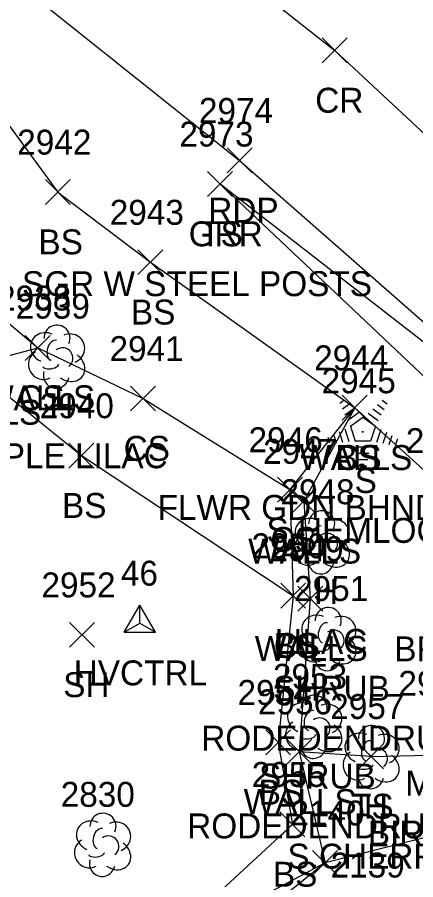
# Model space of a CAD drawing. Extents: x 1499292 to 1501024, y 534584 to 538043.
# Drawn here: x 1499749.5 to 1499781.4, y 537664.7 to 537733.8 of the extents above; entities that cross this region are included whole.
import ezdxf

# ---------------------------------------------------------------- set-up
doc = ezdxf.new("R2010")
doc.units = 0
for name, color, linetype in [('C_A', 7, 'Continuous'), ('C_I', 7, 'Continuous'), ('CPSM', 7, 'Continuous'), ('L_A', 7, 'Continuous'), ('L_C', 7, 'Continuous'), ('L_I', 7, 'Continuous'), ('L_TIC', 7, 'Continuous'), ('LAWA', 7, 'Continuous'), ('LELB', 7, 'Continuous'), ('LSH', 7, 'Continuous'), ('LTC', 7, 'Continuous'), ('LTD', 7, 'Continuous'), ('LWS', 7, 'Continuous'), ('P_A', 7, 'Continuous'), ('P_I', 7, 'Continuous'), ('P_TIC', 7, 'Continuous'), ('PET', 7, 'Continuous'), ('PRC', 7, 'Continuous'), ('R_A', 7, 'Continuous'), ('R_C', 7, 'Continuous'), ('R_I', 7, 'Continuous'), ('R_TIC', 7, 'Continuous'), ('RGR', 7, 'Continuous'), ('S_C', 7, 'Continuous')]:
    doc.layers.add(name, color=color, linetype=linetype)

msp = doc.modelspace()

# ---------------------------------------------------------------- linework, layer by layer
at = {"layer": 'CPSM'}
for p, q in [((1499758.044, 537684.529), (1499759.294, 537686.694)), ((1499760.544, 537684.529), (1499759.294, 537686.694)), ((1499759.294, 537685.25), (1499759.294, 537686.694)), ((1499758.044, 537684.529), (1499759.294, 537685.25)), ((1499759.294, 537685.25), (1499759.294, 537685.25)), ((1499759.294, 537685.25), (1499760.544, 537684.529)), ((1499758.044, 537684.529), (1499760.544, 537684.529))]:
    msp.add_line(p, q, dxfattribs=at)
at = {"layer": 'L_TIC'}
for points in [[(1499751.712, 537718.821), (1499753.712, 537720.821)], [(1499753.712, 537718.821), (1499751.712, 537720.821)], [(1499764.726, 537719.467), (1499766.726, 537721.467)], [(1499766.726, 537719.467), (1499764.726, 537721.467)], [(1499759.138, 537713.193), (1499761.138, 537715.193)], [(1499761.138, 537713.193), (1499759.138, 537715.193)], [(1499750.097, 537706.315), (1499752.097, 537708.315)], [(1499752.097, 537706.315), (1499750.097, 537708.315)], [(1499750.097, 537706.315), (1499752.097, 537708.315)], [(1499752.097, 537706.315), (1499750.097, 537708.315)], [(1499758.552, 537702.258), (1499760.552, 537704.258)], [(1499760.552, 537702.258), (1499758.552, 537704.258)], [(1499775.543, 537701.52), (1499777.543, 537703.52)], [(1499777.543, 537701.52), (1499775.543, 537703.52)], [(1499775.543, 537701.52), (1499777.543, 537703.52)], [(1499777.543, 537701.52), (1499775.543, 537703.52)], [(1499775.543, 537701.52), (1499777.543, 537703.52)], [(1499777.543, 537701.52), (1499775.543, 537703.52)], [(1499753.605, 537697.679), (1499755.605, 537699.679)], [(1499755.605, 537697.679), (1499753.605, 537699.679)], [(1499770.334, 537694.953), (1499772.334, 537696.953)], [(1499772.334, 537694.953), (1499770.334, 537696.953)], [(1499770.334, 537694.953), (1499772.334, 537696.953)], [(1499772.334, 537694.953), (1499770.334, 537696.953)], [(1499771.443, 537694.018), (1499773.443, 537696.018)], [(1499773.443, 537694.018), (1499771.443, 537696.018)], [(1499770.599, 537686.444), (1499772.599, 537688.444)], [(1499772.599, 537686.444), (1499770.599, 537688.444)], [(1499770.599, 537686.444), (1499772.599, 537688.444)], [(1499772.599, 537686.444), (1499770.599, 537688.444)], [(1499771.971, 537686.21), (1499773.971, 537688.21)], [(1499773.971, 537686.21), (1499771.971, 537688.21)], [(1499753.656, 537683.305), (1499755.656, 537685.305)], [(1499755.656, 537683.305), (1499753.656, 537685.305)], [(1499769.394, 537674.679), (1499771.394, 537676.679)], [(1499771.394, 537674.679), (1499769.394, 537676.679)], [(1499771.085, 537673.925), (1499773.085, 537675.925)], [(1499773.085, 537673.925), (1499771.085, 537675.925)], [(1499776.835, 537673.552), (1499778.835, 537675.552)], [(1499778.835, 537673.552), (1499776.835, 537675.552)], [(1499770.532, 537668.102), (1499772.532, 537670.102)], [(1499772.532, 537668.102), (1499770.532, 537670.102)], [(1499773.16, 537665.013), (1499775.16, 537667.013)], [(1499775.16, 537665.013), (1499773.16, 537667.013)], [(1499773.16, 537665.013), (1499775.16, 537667.013)], [(1499775.16, 537665.013), (1499773.16, 537667.013)]]:
    msp.add_lwpolyline(points, dxfattribs=at)
at = {"layer": 'LAWA'}
msp.add_lwpolyline([(1499794.252, 537673.216), (1499784.112, 537668.524), (1499774.16, 537666.013), (1499760.161, 537658.549), (1499756.138, 537654.928), (1499740.504, 537649.758), (1499726.858, 537641.254), (1499716.884, 537640.029), (1499711.646, 537641.29), (1499703.308, 537651.197), (1499688.979, 537659.909), (1499670.84, 537674.411)], dxfattribs=at)
at = {"layer": 'LELB'}
for points in [[(1499673.505, 537786.342), (1499677.07, 537783.592), (1499700.821, 537763.481), (1499719.743, 537752.304), (1499723.657, 537747.33), (1499740.89, 537735.965), (1499752.712, 537719.821), (1499760.138, 537714.193), (1499776.543, 537702.52), (1499783.898, 537695.878)], [(1499765.726, 537720.467), (1499786.683, 537700.702), (1499803.043, 537683.466)], [(1499737.647, 537718.705), (1499751.097, 537707.315), (1499759.552, 537703.258), (1499771.334, 537695.953)], [(1499731.101, 537702.105), (1499743.79, 537705.244), (1499746.925, 537704.877), (1499754.605, 537698.679), (1499771.599, 537687.444), (1499770.394, 537675.679), (1499771.532, 537669.102)], [(1499776.543, 537702.52), (1499771.334, 537695.953), (1499771.599, 537687.444)], [(1499777.835, 537674.552), (1499772.085, 537674.925)], [(1499777.835, 537674.552), (1499786.002, 537674.728)], [(1499771.532, 537669.102), (1499760.161, 537658.549)]]:
    msp.add_lwpolyline(points, dxfattribs=at)
at = {"layer": 'LSH'}
for p, q in [((1499774.365, 537684.016), (1499774.365, 537684.016)), ((1499774.365, 537684.016), (1499774.365, 537684.016)), ((1499773.233, 537676.975), (1499773.233, 537676.975)), ((1499773.233, 537676.975), (1499773.233, 537676.975))]:
    msp.add_line(p, q, dxfattribs=at)
for centre in [(1499774.412, 537685.45), (1499773.28, 537678.409)]:
    msp.add_arc(centre, 1.047, 335.52715, 180.95627, dxfattribs=at)
for centre, major_axis, ratio, start_param, end_param in [((1499773.573, 537684.683), (1.21, -0.512), 0.895232, 1.570796, 4.712389), ((1499775.407, 537684.6), (-1.141, -0.483), 0.949671, 1.570796, 4.712389), ((1499774.157, 537684.474), (-0.208, -0.792), 0.645439, 3.141593, 6.283185), ((1499773.282, 537683.308), (0.584, -1.042), 0.959034, 3.141593, 6.283185), ((1499774.865, 537683.85), (-0.5, 0.667), 0.989748, 3.141593, 6.283185), ((1499775.365, 537683.183), (-1.09, 0.792), 0.841452, 1.570796, 4.712389), ((1499774.365, 537682.516), (0.265, 1.061), 0.942809, 1.570796, 4.712389), ((1499773.907, 537683.266), (-0.625, -0.083), 0.423636, 0, 3.141593), ((1499772.442, 537677.642), (1.21, -0.512), 0.895232, 1.570796, 4.712389), ((1499774.275, 537677.559), (-1.141, -0.483), 0.949671, 1.570796, 4.712389), ((1499773.025, 537677.433), (-0.208, -0.792), 0.645439, 3.141593, 6.283185), ((1499772.15, 537676.267), (0.584, -1.042), 0.959034, 3.141593, 6.283185), ((1499773.733, 537676.808), (-0.5, 0.667), 0.989748, 3.141593, 6.283185), ((1499774.234, 537676.142), (-1.09, 0.792), 0.841452, 1.570796, 4.712389), ((1499772.775, 537676.225), (-0.625, -0.083), 0.423636, 0, 3.141593), ((1499773.234, 537675.475), (0.265, 1.061), 0.942809, 1.570796, 4.712389)]:
    msp.add_ellipse(centre, major_axis=major_axis, ratio=ratio, start_param=start_param, end_param=end_param, dxfattribs=at)
at = {"layer": 'LTC'}
for p, q in [((1499775.336, 537702.888), (1499775.69, 537703.146)), ((1499778.734, 537703.129), (1499779.153, 537702.824)), ((1499775.545, 537702.423), (1499776.074, 537702.807)), ((1499775.755, 537701.957), (1499776.458, 537702.468)), ((1499775.964, 537701.491), (1499776.843, 537702.129)), ((1499777.992, 537702.432), (1499778.671, 537701.938)), ((1499778.363, 537702.78), (1499778.912, 537702.381)), ((1499776.189, 537701.036), (1499777.201, 537701.771)), ((1499777.201, 537701.771), (1499778.198, 537701.046)), ((1499777.621, 537702.084), (1499778.43, 537701.495)), ((1499775.734, 537700.817), (1499776.065, 537699.798)), ((1499776.189, 537701.036), (1499776.576, 537699.843)), ((1499778.198, 537701.046), (1499777.806, 537699.843)), ((1499778.635, 537700.775), (1499778.297, 537699.735)), ((1499774.368, 537700.167), (1499774.52, 537699.699)), ((1499774.824, 537700.384), (1499775.035, 537699.732)), ((1499775.279, 537700.601), (1499775.55, 537699.765)), ((1499779.08, 537700.524), (1499778.792, 537699.64)), ((1499779.524, 537700.274), (1499779.287, 537699.545)), ((1499777.806, 537699.843), (1499776.576, 537699.843)), ((1499779.968, 537700.024), (1499779.782, 537699.45)), ((1499777.768, 537699.343), (1499776.623, 537699.343)), ((1499777.684, 537698.843), (1499776.696, 537698.843)), ((1499777.601, 537698.343), (1499776.769, 537698.343)), ((1499777.517, 537697.843), (1499776.842, 537697.843))]:
    msp.add_line(p, q, dxfattribs=at)
at = {"layer": 'LTD'}
for p, q in [((1499752.598, 537706.666), (1499752.598, 537706.666)), ((1499752.598, 537706.666), (1499752.598, 537706.666)), ((1499773.838, 537691.777), (1499773.838, 537691.777)), ((1499773.838, 537691.777), (1499773.838, 537691.777)), ((1499777.835, 537674.552), (1499777.835, 537674.552)), ((1499777.835, 537674.552), (1499777.835, 537674.552)), ((1499756.287, 537667.508), (1499756.287, 537667.508)), ((1499756.287, 537667.508), (1499756.287, 537667.508))]:
    msp.add_line(p, q, dxfattribs=at)
for centre in [(1499752.644, 537708.1), (1499773.884, 537693.211), (1499777.882, 537675.986), (1499756.334, 537668.942)]:
    msp.add_arc(centre, 1.047, 335.52715, 180.95627, dxfattribs=at)
for centre, major_axis, ratio, start_param, end_param in [((1499751.806, 537707.333), (1.21, -0.512), 0.895232, 1.570796, 4.712389), ((1499753.639, 537707.25), (-1.141, -0.483), 0.949671, 1.570796, 4.712389), ((1499752.389, 537707.125), (-0.208, -0.792), 0.645439, 3.141593, 6.283185), ((1499751.515, 537705.958), (0.584, -1.042), 0.959034, 3.141593, 6.283185), ((1499753.098, 537706.5), (-0.5, 0.667), 0.989748, 3.141593, 6.283185), ((1499753.598, 537705.833), (-1.09, 0.792), 0.841452, 1.570796, 4.712389), ((1499752.14, 537705.916), (-0.625, -0.083), 0.423636, 0, 3.141593), ((1499752.598, 537705.166), (0.265, 1.061), 0.942809, 1.570796, 4.712389), ((1499773.046, 537692.444), (1.21, -0.512), 0.895232, 1.570796, 4.712389), ((1499774.879, 537692.361), (-1.141, -0.483), 0.949671, 1.570796, 4.712389), ((1499773.629, 537692.235), (-0.208, -0.792), 0.645439, 3.141593, 6.283185), ((1499774.338, 537691.611), (-0.5, 0.667), 0.989748, 3.141593, 6.283185), ((1499772.754, 537691.069), (0.584, -1.042), 0.959034, 3.141593, 6.283185), ((1499774.838, 537690.944), (-1.09, 0.792), 0.841452, 1.570796, 4.712389), ((1499773.379, 537691.027), (-0.625, -0.083), 0.423636, 0, 3.141593), ((1499773.838, 537690.277), (0.265, 1.061), 0.942809, 1.570796, 4.712389), ((1499777.044, 537675.218), (1.21, -0.512), 0.895232, 1.570796, 4.712389), ((1499777.627, 537675.01), (-0.208, -0.792), 0.645439, 3.141593, 6.283185), ((1499778.877, 537675.135), (-1.141, -0.483), 0.949671, 1.570796, 4.712389), ((1499778.335, 537674.385), (-0.5, 0.667), 0.989748, 3.141593, 6.283185), ((1499776.752, 537673.843), (0.584, -1.042), 0.959034, 3.141593, 6.283185), ((1499778.835, 537673.719), (-1.09, 0.792), 0.841452, 1.570796, 4.712389), ((1499777.377, 537673.802), (-0.625, -0.083), 0.423636, 0, 3.141593), ((1499777.836, 537673.052), (0.265, 1.061), 0.942809, 1.570796, 4.712389), ((1499755.495, 537668.175), (1.21, -0.512), 0.895232, 1.570796, 4.712389), ((1499757.329, 537668.092), (-1.141, -0.483), 0.949671, 1.570796, 4.712389), ((1499756.079, 537667.967), (-0.208, -0.792), 0.645439, 3.141593, 6.283185), ((1499756.787, 537667.342), (-0.5, 0.667), 0.989748, 3.141593, 6.283185), ((1499755.204, 537666.8), (0.584, -1.042), 0.959034, 3.141593, 6.283185), ((1499757.287, 537666.675), (-1.09, 0.792), 0.841452, 1.570796, 4.712389), ((1499755.829, 537666.758), (-0.625, -0.083), 0.423636, 0, 3.141593), ((1499756.288, 537666.008), (0.265, 1.061), 0.942809, 1.570796, 4.712389)]:
    msp.add_ellipse(centre, major_axis=major_axis, ratio=ratio, start_param=start_param, end_param=end_param, dxfattribs=at)
at = {"layer": 'LWS'}
for points in [[(1499743.79, 537705.244), (1499746.766, 537706.161), (1499751.097, 537707.315)], [(1499776.543, 537702.52), (1499772.443, 537695.018), (1499772.971, 537687.21), (1499772.085, 537674.925)], [(1499772.085, 537674.925), (1499774.16, 537666.013)], [(1499774.16, 537666.013), (1499761.796, 537656.084), (1499756.809, 537653.017), (1499742.21, 537646.621), (1499726.858, 537641.254)]]:
    msp.add_lwpolyline(points, dxfattribs=at)
at = {"layer": 'P_TIC'}
for points in [[(1499773.937, 537730.181), (1499775.937, 537732.181)], [(1499775.937, 537730.181), (1499773.937, 537732.181)], [(1499766.298, 537721.36), (1499768.298, 537723.36)], [(1499768.298, 537721.36), (1499766.298, 537723.36)]]:
    msp.add_lwpolyline(points, dxfattribs=at)
at = {"layer": 'PET'}
msp.add_lwpolyline([(1499310.023, 537983.746), (1499343.075, 537969.541), (1499383.731, 537949.439), (1499427.71, 537927.425), (1499464.171, 537907.983), (1499500.199, 537887.497), (1499544.495, 537863.142), (1499587.74, 537838.677), (1499616.247, 537822.183), (1499651.021, 537801.554), (1499676.536, 537785.628), (1499704.158, 537768.574), (1499722.55, 537756.398), (1499745.414, 537739.8), (1499767.298, 537722.36), (1499790.892, 537701.646), (1499806.057, 537686.036), (1499813.912, 537693.068), (1499820.533, 537699.08)], dxfattribs=at)
at = {"layer": 'PRC'}
msp.add_lwpolyline([(1499314.647, 537995.238), (1499351.896, 537980.059), (1499390.853, 537960.785), (1499432.771, 537938.063), (1499470.255, 537918.917), (1499503.529, 537899.736), (1499550.301, 537873.589), (1499594.281, 537849.334), (1499631.071, 537828.01), (1499665.93, 537807.267), (1499699.614, 537786.782), (1499728.317, 537767.815), (1499774.937, 537731.181), (1499796.918, 537710.716), (1499813.912, 537693.068)], dxfattribs=at)
at = {"layer": 'R_TIC'}
for points in [[(1499764.726, 537719.467), (1499766.726, 537721.467)], [(1499766.726, 537719.467), (1499764.726, 537721.467)]]:
    msp.add_lwpolyline(points, dxfattribs=at)
at = {"layer": 'RGR'}
msp.add_lwpolyline([(1499765.726, 537720.467), (1499790.299, 537701.407), (1499805.483, 537685.598)], dxfattribs=at)

# ---------------------------------------------------------------- texts
at = {"layer": 'C_A'}
msp.add_text('HVCTRL', height=2, dxfattribs=at).set_placement((1499753.987, 537680.25))
at = {"layer": 'C_I'}
msp.add_text('46', height=2, dxfattribs=at).set_placement((1499757.774, 537688.25))
at = {"layer": 'L_A'}
for s, p in [('TS', (1499764.136, 537715.467)), ('BS', (1499751.153, 537714.821)), ('BS', (1499758.579, 537709.193)), ('WALLS', (1499746.641, 537702.315)), ('CS', (1499749.538, 537702.315)), ('H', (1499752.031, 537701.666)), ('WALLS', (1499742.31, 537701.161)), ('CS', (1499757.993, 537698.258)), ('WALLS', (1499772.086, 537697.52)), ('CS', (1499774.984, 537697.52)), ('BS', (1499774.984, 537697.52)), ('S', (1499776.526, 537695.68)), ('BS', (1499753.046, 537693.679)), ('CS', (1499769.775, 537690.953)), ('CS', (1499769.775, 537690.953)), ('WALLS', (1499767.986, 537690.018)), ('H', (1499773.271, 537686.777)), ('WALLS', (1499768.515, 537682.21)), ('CS', (1499770.04, 537682.444)), ('BS', (1499770.04, 537682.444)), ('SH', (1499753.144, 537679.305)), ('SHRUB', (1499769.995, 537679.016)), ('SHRUB', (1499768.863, 537671.975)), ('MMF', (1499780.587, 537671.41)), ('BS', (1499768.835, 537670.679)), ('WALLS', (1499767.629, 537669.925)), ('TS', (1499776.245, 537669.552)), ('H', (1499777.268, 537669.552)), ('BS', (1499769.973, 537664.102))]:
    msp.add_text(s, height=2, dxfattribs=at).set_placement(p)
at = {"layer": 'L_C'}
for s, p in [('S.MAPLE LILAC', (1499741.755, 537697.666)), ('FLWR GDN BHND WAL', (1499760.716, 537693.52)), ('S.HEMLOCK', (1499769.455, 537691.68)), ('LILAC', (1499770.113, 537682.777)), ('RODEDENDRUM', (1499764.223, 537675.016)), ('RODEDENDRUM', (1499763.092, 537667.975)), ('BIRDBOX', (1499777.587, 537667.41)), ('S.CHERRY', (1499771.142, 537665.552))]:
    msp.add_text(s, height=2, dxfattribs=at).set_placement(p)
at = {"layer": 'L_I'}
for s, p in [('2973', (1499762.466, 537723.467)), ('2942', (1499749.453, 537722.821)), ('2943', (1499756.879, 537717.193)), ('2938', (1499747.838, 537710.315)), ('2938', (1499747.838, 537710.315)), ('2939', (1499749.33, 537709.666)), ('2941', (1499756.86, 537706.258)), ('2944', (1499773.283, 537705.52)), ('2944', (1499773.283, 537705.52)), ('2944', (1499773.283, 537705.52)), ('2945', (1499773.881, 537703.68)), ('2940', (1499751.259, 537701.679)), ('2946', (1499768.019, 537698.953)), ('2946', (1499768.019, 537698.953)), ('2972', (1499780.639, 537698.878)), ('2972', (1499780.639, 537698.878)), ('2947', (1499769.183, 537698.018)), ('2948', (1499770.578, 537694.777)), ('2950', (1499768.253, 537690.444)), ('2950', (1499768.253, 537690.444)), ('2949', (1499769.704, 537690.21)), ('2952', (1499751.396, 537687.305)), ('2951', (1499771.672, 537687.016)), ('2953', (1499769.974, 537679.975)), ('2958', (1499780.044, 537679.41)), ('2954', (1499767.134, 537678.679)), ('2956', (1499768.77, 537677.925)), ('2957', (1499774.575, 537677.552)), ('2957', (1499774.575, 537677.552)), ('2955', (1499768.272, 537672.102)), ('2830', (1499752.941, 537670.508)), ('2140', (1499771.38, 537669.013)), ('2140', (1499771.38, 537669.013)), ('2139', (1499774.603, 537664.837))]:
    msp.add_text(s, height=2, dxfattribs=at).set_placement(p)
at = {"layer": 'LTC'}
msp.add_text('.', height=1.037, rotation=270, dxfattribs=at).set_placement((1499777.083, 537700.784))
at = {"layer": 'P_A'}
for s, p in [('CR', (1499773.37, 537726.181)), ('RDP', (1499764.786, 537717.36))]:
    msp.add_text(s, height=2, dxfattribs=at).set_placement(p)
at = {"layer": 'P_I'}
msp.add_text('2974', height=2, dxfattribs=at).set_placement((1499764.038, 537725.36))
at = {"layer": 'R_A'}
msp.add_text('GRR', height=2, dxfattribs=at).set_placement((1499763.214, 537715.467))
at = {"layer": 'R_C'}
msp.add_text('SGR W STEEL POSTS', height=2, dxfattribs=at).set_placement((1499749.836, 537711.467))
at = {"layer": 'R_I'}
msp.add_text('2973', height=2, dxfattribs=at).set_placement((1499762.466, 537723.467))
at = {"layer": 'S_C'}
msp.add_text('BRIDGE 15 VT 125', height=2, dxfattribs=at).set_placement((1499779.712, 537682.179))

doc.saveas('drawing.dxf')
